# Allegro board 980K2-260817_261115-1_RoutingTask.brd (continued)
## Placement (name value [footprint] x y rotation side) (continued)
NOREF#1103  -  []  258.97 211.91 90 top
NOREF#1104  -  []  238.64 173.37 90 top
NOREF#1105  -  []  206.32 269.17 0 top
NOREF#1106  -  []  173.34 17.15 0 top
NOREF#1107  -  []  276.57 258.18 0 top
NOREF#1108  -  []  266.69 297.01 90 top
NOREF#1109  -  []  268.78 244.35 0 top
NOREF#1110  -  []  186.01 195.7 90 top
NOREF#1111  -  []  231.98 286.59 90 top
NOREF#1112  -  []  201.75 266.13 0 top
NOREF#1113  -  []  236.84 167.33 0 top
NOREF#1114  -  []  196.02 181.47 0 top
NOREF#1115  -  []  244.61 294.89 90 top
NOREF#1116  -  []  283.84 205.58 0 top
NOREF#1117  -  []  235.17 216.75 90 top
NOREF#1118  -  []  150.41 228.7 90 top
NOREF#1119  -  []  259.08 268.59 0 top
NOREF#1120  -  []  279.24 184.35 0 top
NOREF#1121  -  []  239.27 200.97 90 top
NOREF#1122  -  []  136.83 227.03 0 top
NOREF#1123  -  []  224.16 256.43 90 top
NOREF#1124  -  []  180.83 203.76 90 top
NOREF#1125  -  []  146.28 197.85 90 top
NOREF#1126  -  []  280.23 176.17 90 top
NOREF#1127  -  []  263.36 198.18 0 top
NOREF#1128  -  []  197.18 236.17 90 top
NOREF#1129  -  []  149.24 245.31 90 top
NOREF#1130  -  []  273.56 173.37 90 top
NOREF#1131  -  []  153.95 196.75 0 top
NOREF#1132  -  []  187.43 284.11 0 top
NOREF#1133  -  []  147.43 224.11 0 top
NOREF#1134  -  []  241.75 206.13 0 top
NOREF#1135  -  []  268.81 255.7 90 top
NOREF#1136  -  []  187.45 269.24 0 top
NOREF#1137  -  []  253.62 229.09 90 top
NOREF#1138  -  []  228.78 184.35 0 top
NOREF#1139  -  []  273.76 195.7 90 top
NOREF#1140  -  []  279.4 214.54 0 top
NOREF#1141  -  []  173.64 239.09 0 top
NOREF#1142  -  []  134.07 210.89 90 top
NOREF#1143  -  []  283.97 273.09 90 top
NOREF#1144  -  []  222.81 257.6 0 top
NOREF#1145  -  []  229.72 215.77 0 top
NOREF#1146  -  []  239.27 214.21 0 top
NOREF#1147  -  []  188.44 181.72 90 top
NOREF#1148  -  []  272.87 248.11 90 top
NOREF#1149  -  []  174.43 232.23 0 top
NOREF#1150  -  []  192.25 222.59 90 top
NOREF#1151  -  []  150.56 252.5 0 top
NOREF#1152  -  []  193.39 257.85 90 top
NOREF#1153  -  []  258.35 207.01 0 top
NOREF#1154  -  []  232.72 257.6 0 top
NOREF#1155  -  []  135.66 184.35 0 top
NOREF#1156  -  []  155.15 176.17 90 top
NOREF#1157  -  []  239.65 212.56 0 top
NOREF#1158  -  []  199.4 204.45 90 top
NOREF#1159  -  []  267.99 178.35 0 top
NOREF#1160  -  []  203.97 202.09 0 top
NOREF#1161  -  []  259.55 294.49 0 top
NOREF#1162  -  []  227.43 224.11 0 top
NOREF#1163  -  []  155.68 173.69 90 top
NOREF#1164  -  []  243.84 268.62 0 top
NOREF#1165  -  []  128.45 235.2 0 top
NOREF#1166  -  []  208.54 267.5 90 top
NOREF#1167  -  []  164.95 270.32 90 top
NOREF#1168  -  []  234.33 264.33 90 top
NOREF#1169  -  []  169.52 210.32 90 top
NOREF#1170  -  []  192.72 252.78 0 top
NOREF#1171  -  []  216 456.29 90 top
NOREF#1172  -  []  219.08 208.59 0 top
NOREF#1173  -  []  220.43 224.38 90 top
NOREF#1174  -  []  283.84 204.78 90 top
NOREF#1175  -  []  187.77 197.6 0 top
NOREF#1176  -  []  106.58 18.69 90 top
NOREF#1177  -  []  197.03 238.07 0 top
NOREF#1178  -  []  203.97 273.09 90 top
NOREF#1179  -  []  212.87 287.4 90 top
NOREF#1180  -  []  175.24 201.55 90 top
NOREF#1181  -  []  276.52 276.55 0 top
NOREF#1182  -  []  186.96 191.6 90 top
NOREF#1183  -  []  277.37 180.3 90 top
NOREF#1184  -  []  253.62 289.09 90 top
NOREF#1185  -  []  180.95 201.55 90 top
NOREF#1186  -  []  277.25 256.75 0 top
NOREF#1187  -  []  259.39 16.49 0 top
NOREF#1188  -  []  236.02 252.78 0 top
NOREF#1189  -  []  268.35 223.79 90 top
NOREF#1190  -  []  195.68 173.69 0 top
NOREF#1191  -  []  231.11 193.35 0 top
NOREF#1192  -  []  88.16 165.19 0 top
NOREF#1193  -  []  245.38 286.23 0 top
NOREF#1194  -  []  282.26 176.17 90 top
NOREF#1195  -  []  139.08 208.59 0 top
NOREF#1196  -  []  215.84 262.57 90 top
NOREF#1197  -  []  163.84 270.87 90 top
NOREF#1198  -  []  196.57 198.18 0 top
NOREF#1199  -  []  253.36 201.22 0 top
NOREF#1200  -  []  244.61 234.89 90 top
NOREF#1201  -  []  238.11 232.1 0 top
NOREF#1202  -  []  159.4 200.64 90 top
NOREF#1203  -  []  229.84 273.7 0 top
NOREF#1204  -  []  266.96 251.6 90 top
NOREF#1205  -  []  148.32 245.63 90 top
NOREF#1206  -  []  165.38 226.23 0 top
NOREF#1207  -  []  276.02 252.78 0 top
NOREF#1208  -  []  227.8 204.99 90 top
NOREF#1209  -  []  88.16 144.87 0 top
NOREF#1210  -  []  229.67 250.01 0 top
NOREF#1211  -  []  251.05 229.49 0 top
NOREF#1212  -  []  199.72 214.65 90 top
NOREF#1213  -  []  147.77 236.37 0 top
NOREF#1214  -  []  263.49 247.06 90 top
NOREF#1215  -  []  266.16 260.17 90 top
NOREF#1216  -  []  148.78 184.35 0 top
NOREF#1217  -  []  156.54 167 0 top
NOREF#1218  -  []  191.91 256.43 90 top
NOREF#1219  -  []  317.15 392.33 90 top
NOREF#1220  -  []  323.77 454.29 90 top
NOREF#1221  -  []  231.71 171.3 0 top
NOREF#1222  -  []  187.77 241.47 0 top
NOREF#1223  -  []  193.39 253.03 90 top
NOREF#1224  -  []  216 456.29 0 top
NOREF#1225  -  []  168.54 208.95 0 top
NOREF#1226  -  []  179.55 180.49 90 top
NOREF#1227  -  []  263.49 197.85 90 top
NOREF#1228  -  []  269.72 215.77 0 top
NOREF#1229  -  []  149.84 273.7 90 top
NOREF#1230  -  []  248.42 261.77 0 top
NOREF#1231  -  []  230.88 228.6 90 top
NOREF#1232  -  []  261.55 269.94 90 top
NOREF#1233  -  []  209.52 270.32 90 top
NOREF#1234  -  []  252.87 227.4 90 top
NOREF#1235  -  []  168.54 202.09 0 top
NOREF#1236  -  []  227.77 197.6 0 top
NOREF#1237  -  []  236.57 245.63 0 top
NOREF#1238  -  []  268.78 244.35 0 top
NOREF#1239  -  []  269.86 17.15 0 top
NOREF#1240  -  []  183.49 253.03 90 top
NOREF#1241  -  []  186.16 258.18 0 top
NOREF#1242  -  []  148.32 258.18 0 top
NOREF#1243  -  []  254.43 232.23 0 top
NOREF#1244  -  []  130.52 295.42 90 top
NOREF#1245  -  []  259.55 234.49 0 top
NOREF#1246  -  []  168.54 204.45 90 top
NOREF#1247  -  []  186.83 251.93 0 top
NOREF#1248  -  []  324.88 21.69 90 top
NOREF#1249  -  []  231.73 172.54 0 top
NOREF#1250  -  []  236.57 185.63 0 top
NOREF#1251  -  []  160.23 176.17 90 top
NOREF#1252  -  []  237.25 191.93 0 top
NOREF#1253  -  []  194.39 286.59 90 top
NOREF#1254  -  []  239.06 178.07 0 top
NOREF#1255  -  []  157.37 191.6 90 top
NOREF#1256  -  []  171.22 234.89 90 top
NOREF#1257  -  []  254.09 204.23 90 top
NOREF#1258  -  []  203.97 265.9 0 top
NOREF#1259  -  []  195.17 276.75 90 top
NOREF#1260  -  []  156.57 185.63 90 top
NOREF#1261  -  []  269.24 185.31 90 top
NOREF#1262  -  []  243.97 264.45 90 top
NOREF#1263  -  []  208.94 281.73 0 top
NOREF#1264  -  []  203.84 211.67 0 top
NOREF#1265  -  []  288.42 260.97 90 top
NOREF#1266  -  []  271.91 191.6 90 top
NOREF#1267  -  []  89.76 164.74 90 top
NOREF#1268  -  []  231.11 200.17 90 top
NOREF#1269  -  []  156.02 197.6 0 top
NOREF#1270  -  []  150.41 168.7 90 top
NOREF#1271  -  []  216.98 265.11 90 top
NOREF#1272  -  []  157.92 190.01 0 top
NOREF#1273  -  []  163.84 200.97 90 top
NOREF#1274  -  []  270.48 235.77 0 top
NOREF#1275  -  []  277.37 196.43 90 top
NOREF#1276  -  []  283.97 213.09 90 top
NOREF#1277  -  []  161.75 266.13 0 top
NOREF#1278  -  []  139.08 203.76 0 top
NOREF#1279  -  []  123.92 229.94 0 top
NOREF#1280  -  []  189.84 224.11 0 top
NOREF#1281  -  []  279.27 274.21 0 top
NOREF#1282  -  []  122.2 178.35 0 top
NOREF#1283  -  []  129.17 231.95 0 top
NOREF#1284  -  []  250.92 231.95 90 top
NOREF#1285  -  []  151.11 198.18 0 top
NOREF#1286  -  []  106.68 128.02 90 top
NOREF#1287  -  []  188.32 245.63 90 top
NOREF#1288  -  []  155.49 228.7 90 top
NOREF#1289  -  []  227.23 18.69 90 top
NOREF#1290  -  []  269.12 256.43 90 top
NOREF#1291  -  []  179.73 178.35 0 top
NOREF#1292  -  []  172.55 224.49 0 top
NOREF#1293  -  []  157.71 173.69 0 top
NOREF#1294  -  []  232.25 278.02 90 top
NOREF#1295  -  []  222.87 273.02 0 top
NOREF#1296  -  []  265.61 197.6 0 top
NOREF#1297  -  []  156.52 221.12 0 top
NOREF#1298  -  []  283.97 274.54 0 top
NOREF#1299  -  []  132.26 248.4 0 top
NOREF#1300  -  []  224.16 191.6 90 top
NOREF#1301  -  []  153.95 191.93 0 top
NOREF#1302  -  []  192.13 224.66 0 top
NOREF#1303  -  []  188.78 184.35 0 top
NOREF#1304  -  []  163.97 204.45 90 top
NOREF#1305  -  []  196.02 197.6 0 top
NOREF#1306  -  []  271.98 286.59 90 top
NOREF#1307  -  []  231.79 251.93 0 top
NOREF#1308  -  []  100.95 17.15 0 top
NOREF#1309  -  []  190.56 197.6 0 top
NOREF#1310  -  []  218.95 204.09 0 top
NOREF#1311  -  []  114.61 17.78 0 top
NOREF#1312  -  []  266.96 256.43 90 top
NOREF#1313  -  []  135.43 276.18 0 top
NOREF#1314  -  []  196.8 274.65 90 top
NOREF#1315  -  []  124.32 291.95 90 top
NOREF#1316  -  []  283.97 267.5 90 top
NOREF#1317  -  []  152.63 172.86 0 top
NOREF#1318  -  []  124.44 232.28 90 top
NOREF#1319  -  []  201.75 272.22 0 top
NOREF#1320  -  []  279.4 274.54 0 top
NOREF#1321  -  []  226.96 196.43 90 top
NOREF#1322  -  []  148.99 256.75 0 top
NOREF#1323  -  []  211.25 244.35 0 top
NOREF#1324  -  []  149.84 213.7 90 top
NOREF#1325  -  []  271.11 260.17 90 top
NOREF#1326  -  []  276.8 274.65 90 top
NOREF#1327  -  []  202.85 237.22 0 top
NOREF#1328  -  []  281.41 227.9 90 top
NOREF#1329  -  []  251.05 232.28 90 top
NOREF#1330  -  []  229.72 281.62 0 top
NOREF#1331  -  []  235.92 190.88 90 top
NOREF#1332  -  []  221.55 262.57 90 top
NOREF#1333  -  []  186.28 253.03 90 top
NOREF#1334  -  []  279.4 273.09 90 top
NOREF#1335  -  []  157.5 185.31 90 top
NOREF#1336  -  []  258.83 292.23 0 top
NOREF#1337  -  []  171.05 185.49 90 top
NOREF#1338  -  []  226.01 195.7 90 top
NOREF#1339  -  []  188.44 253.03 90 top
NOREF#1340  -  []  156.84 227.33 0 top
NOREF#1341  -  []  208.54 200.64 90 top
NOREF#1342  -  []  180.59 184.98 90 top
NOREF#1343  -  []  167.74 396.29 0 top
NOREF#1344  -  []  278.91 172.21 90 top
NOREF#1345  -  []  236.57 253.35 0 top
NOREF#1346  -  []  241.75 209.17 0 top
NOREF#1347  -  []  258.95 201.55 0 top
NOREF#1348  -  []  138.35 204.47 0 top
NOREF#1349  -  []  175.24 261.55 90 top
NOREF#1350  -  []  155.05 283.39 0 top
NOREF#1351  -  []  156.7 197.85 90 top
NOREF#1352  -  []  248.54 264.45 90 top
NOREF#1353  -  []  196.5 392.33 90 top
NOREF#1354  -  []  180.83 265.79 90 top
NOREF#1355  -  []  163.97 270.55 90 top
NOREF#1356  -  []  270.77 219.22 90 top
NOREF#1357  -  []  271.76 167.33 0 top
NOREF#1358  -  []  248.54 265.9 0 top
NOREF#1359  -  []  164.44 292.28 90 top
NOREF#1360  -  []  276.57 253.35 0 top
NOREF#1361  -  []  161.75 269.17 0 top
NOREF#1362  -  []  279.27 201.77 0 top
NOREF#1363  -  []  250.89 262.32 0 top
NOREF#1364  -  []  191.11 253.35 0 top
NOREF#1365  -  []  191.19 218.07 0 top
NOREF#1366  -  []  268.78 288.49 0 top
NOREF#1367  -  []  227.3 226.19 0 top
NOREF#1368  -  []  189.84 213.7 90 top
NOREF#1369  -  []  184.04 251.93 0 top
NOREF#1370  -  []  145.61 197.6 0 top
NOREF#1371  -  []  168.94 221.73 0 top
NOREF#1372  -  []  109.55 389.27 90 top
NOREF#1373  -  []  251.05 292.28 90 top
NOREF#1374  -  []  264.04 256.75 0 top
NOREF#1375  -  []  225.61 257.6 0 top
NOREF#1376  -  []  167.04 299.09 0 top
NOREF#1377  -  []  185.41 213.02 90 top
NOREF#1378  -  []  226.16 258.18 0 top
NOREF#1379  -  []  196.8 225.06 90 top
NOREF#1380  -  []  149.72 286.19 0 top
NOREF#1381  -  []  150.6 173.69 0 top
NOREF#1382  -  []  207.04 299.09 0 top
NOREF#1383  -  []  275.15 236.17 90 top
NOREF#1384  -  []  152.25 218.02 0 top
NOREF#1385  -  []  151.91 256.43 90 top
NOREF#1386  -  []  279.22 190.88 90 top
NOREF#1387  -  []  243.97 207.5 90 top
NOREF#1388  -  []  231.46 167 0 top
NOREF#1389  -  []  220.43 284.38 90 top
NOREF#1390  -  []  152.25 222.59 0 top
NOREF#1391  -  []  153.56 233.37 90 top
NOREF#1392  -  []  212.55 190.49 90 top
NOREF#1393  -  []  273.94 251.93 0 top
NOREF#1394  -  []  231.24 193.03 90 top
NOREF#1395  -  []  255.11 261.22 90 top
NOREF#1396  -  []  236.8 285.06 90 top
NOREF#1397  -  []  241.41 167.9 90 top
NOREF#1398  -  []  248.54 260.64 90 top
NOREF#1399  -  []  229.12 240.3 90 top
NOREF#1400  -  []  266.83 196.75 0 top
NOREF#1401  -  []  196.33 167.9 90 top
NOREF#1402  -  []  128.48 456.29 0 top
NOREF#1403  -  []  156.1 280.99 90 top
NOREF#1404  -  []  231.53 173.37 90 top
NOREF#1405  -  []  191.98 226.59 90 top
NOREF#1406  -  []  274.07 196.43 90 top
NOREF#1407  -  []  271.19 218.07 0 top
NOREF#1408  -  []  216.55 254.49 90 top
NOREF#1409  -  []  199.4 268.95 0 top
NOREF#1410  -  []  209.52 210.32 90 top
NOREF#1411  -  []  139.72 213.6 90 top
NOREF#1412  -  []  185.61 252.78 0 top
NOREF#1413  -  []  272.11 231.4 0 top
NOREF#1414  -  []  142.03 289.03 90 top
NOREF#1415  -  []  239.27 268.62 0 top
NOREF#1416  -  []  134.51 203.76 0 top
NOREF#1417  -  []  148.99 240.62 0 top
NOREF#1418  -  []  209.05 292.28 0 top
NOREF#1419  -  []  242.44 232.28 0 top
NOREF#1420  -  []  187.8 265.39 90 top
NOREF#1421  -  []  239.4 214.54 0 top
NOREF#1422  -  []  231.53 233.37 90 top
NOREF#1423  -  []  186.7 283.04 90 top
NOREF#1424  -  []  156.61 233.37 90 top
NOREF#1425  -  []  187.77 257.6 0 top
NOREF#1426  -  []  248.54 268.95 0 top
NOREF#1427  -  []  146.17 226.14 90 top
NOREF#1428  -  []  223.36 253.35 0 top
NOREF#1429  -  []  195.68 233.69 0 top
NOREF#1430  -  []  191.11 258.18 0 top
NOREF#1431  -  []  237.04 244.35 0 top
NOREF#1432  -  []  181.85 232.5 0 top
NOREF#1433  -  []  235.17 281.32 90 top
NOREF#1434  -  []  159.4 260.64 90 top
NOREF#1435  -  []  164.95 272.86 90 top
NOREF#1436  -  []  208.42 204.78 90 top
NOREF#1437  -  []  178.97 271.91 90 top
NOREF#1438  -  []  221.59 234.15 0 top
NOREF#1439  -  []  242.57 231.95 0 top
NOREF#1440  -  []  206.32 212.22 0 top
NOREF#1441  -  []  205.38 226.23 0 top
NOREF#1442  -  []  179.08 201.22 0 top
NOREF#1443  -  []  269.72 275.77 0 top
NOREF#1444  -  []  195.17 216.75 90 top
NOREF#1445  -  []  172.37 392.33 90 top
NOREF#1446  -  []  159.4 273.09 90 top
NOREF#1447  -  []  243.97 267.5 90 top
NOREF#1448  -  []  176.38 204.09 90 top
NOREF#1449  -  []  274.33 267.37 90 top
NOREF#1450  -  []  214.43 232.23 0 top
NOREF#1451  -  []  236.52 221.12 0 top
NOREF#1452  -  []  277.37 256.43 90 top
NOREF#1453  -  []  277.59 175.77 0 top
NOREF#1454  -  []  318.12 17.15 0 top
NOREF#1455  -  []  187.43 284.11 90 top
NOREF#1456  -  []  148.44 253.03 90 top
NOREF#1457  -  []  254.09 267.27 90 top
NOREF#1458  -  []  260.95 206.12 90 top
NOREF#1459  -  []  222.81 252.78 0 top
NOREF#1460  -  []  235.68 233.69 0 top
NOREF#1461  -  []  269.55 248.99 90 top
NOREF#1462  -  []  133.24 261.55 0 top
NOREF#1463  -  []  261.55 262.57 90 top
NOREF#1464  -  []  227.43 224.11 90 top
NOREF#1465  -  []  199.4 213.09 90 top
NOREF#1466  -  []  231.76 227.33 0 top
NOREF#1467  -  []  149.84 279.54 0 top
NOREF#1468  -  []  135.82 266.44 0 top
NOREF#1469  -  []  271.11 198.18 0 top
NOREF#1470  -  []  253.64 299.09 0 top
NOREF#1471  -  []  239.27 267.82 90 top
NOREF#1472  -  []  163.84 201.77 0 top
NOREF#1473  -  []  276.8 225.06 90 top
NOREF#1474  -  []  226.01 250.88 90 top
NOREF#1475  -  []  151.46 227 0 top
NOREF#1476  -  []  272.13 280.09 0 top
NOREF#1477  -  []  236.02 181.47 0 top
NOREF#1478  -  []  279.4 202.09 0 top
NOREF#1479  -  []  254.09 200.42 90 top
NOREF#1480  -  []  173.36 201.22 0 top
NOREF#1481  -  []  278.11 232.1 0 top
NOREF#1482  -  []  154.39 226.59 90 top
NOREF#1483  -  []  220.95 261.55 90 top
NOREF#1484  -  []  193.76 250.88 90 top
NOREF#1485  -  []  268.19 187.71 0 top
NOREF#1486  -  []  138.85 181.15 90 top
NOREF#1487  -  []  168.54 200.64 90 top
NOREF#1488  -  []  288.42 261.77 0 top
NOREF#1489  -  []  180.95 264.09 90 top
NOREF#1490  -  []  155.58 202.67 90 top
NOREF#1491  -  []  237.71 233.69 90 top
NOREF#1492  -  []  275.17 272.17 90 top
NOREF#1493  -  []  177.29 247.78 0 top
NOREF#1494  -  []  169.17 231.95 0 top
NOREF#1495  -  []  273.39 193.03 90 top
NOREF#1496  -  []  261.55 202.57 90 top
NOREF#1497  -  []  85.84 157.62 0 top
NOREF#1498  -  []  243.84 265.58 0 top
NOREF#1499  -  []  268.44 253.03 90 top
NOREF#1500  -  []  193.76 255.7 90 top
NOREF#1501  -  []  147.43 284.11 0 top
NOREF#1502  -  []  178.97 18.69 0 top
NOREF#1503  -  []  232.13 224.66 0 top
NOREF#1504  -  []  261.85 246.47 0 top
NOREF#1505  -  []  154.33 267.37 90 top
NOREF#1506  -  []  151.24 253.03 90 top
NOREF#1507  -  []  151.95 178.07 0 top
NOREF#1508  -  []  184.16 191.6 90 top
NOREF#1509  -  []  156.7 241.72 90 top
NOREF#1510  -  []  230.2 389.27 90 top
NOREF#1511  -  []  276.7 197.85 90 top
NOREF#1512  -  []  236.57 185.63 90 top
NOREF#1513  -  []  222.6 82.65 0 top
NOREF#1514  -  []  217.25 236.5 90 top
NOREF#1515  -  []  122.44 292.28 0 top
NOREF#1516  -  []  220.63 392.33 90 top
NOREF#1517  -  []  267.77 241.47 0 top
NOREF#1518  -  []  106.83 148.19 90 top
NOREF#1519  -  []  137.28 272.5 0 top
NOREF#1520  -  []  266.01 184.91 90 top
NOREF#1521  -  []  169.52 270.32 90 top
NOREF#1522  -  []  241.75 212.22 0 top
NOREF#1523  -  []  254.43 292.23 0 top
NOREF#1524  -  []  163.4 296.38 0 top
NOREF#1525  -  []  278.64 173.37 90 top
NOREF#1526  -  []  150.88 168.6 90 top
NOREF#1527  -  []  197.71 233.69 90 top
NOREF#1528  -  []  159.4 268.95 0 top
NOREF#1529  -  []  293.99 17.15 90 top
NOREF#1530  -  []  191.98 280.75 90 top
NOREF#1531  -  []  272.11 171.4 0 top
NOREF#1532  -  []  184.04 185.96 0 top
NOREF#1533  -  []  236.84 227.33 0 top
NOREF#1534  -  []  226.01 190.88 90 top
NOREF#1535  -  []  191.85 18.69 0 top
NOREF#1536  -  []  185.41 273.02 90 top
NOREF#1537  -  []  224.04 245.96 0 top
NOREF#1538  -  []  150.21 82.65 0 top
NOREF#1539  -  []  226.16 226.14 90 top
NOREF#1540  -  []  168.54 265.9 0 top
NOREF#1541  -  []  139.55 240.49 90 top
NOREF#1542  -  []  186.7 223.05 90 top
NOREF#1543  -  []  276.38 181.15 90 top
NOREF#1544  -  []  156.79 231.3 0 top
NOREF#1545  -  []  155.05 278.82 0 top
NOREF#1546  -  []  268.32 242.05 0 top
NOREF#1547  -  []  235.56 175.77 0 top
NOREF#1548  -  []  149.84 224.11 0 top
NOREF#1549  -  []  194.33 207.37 90 top
NOREF#1550  -  []  179.08 268.59 0 top
NOREF#1551  -  []  236.33 167.9 90 top
NOREF#1552  -  []  250.89 209.17 0 top
NOREF#1553  -  []  197.04 244.35 0 top
NOREF#1554  -  []  235.05 278.82 0 top
NOREF#1555  -  []  279.06 178.07 0 top
NOREF#1556  -  []  138.74 83.81 0 top
NOREF#1557  -  []  177.29 187.78 0 top
NOREF#1558  -  []  237.74 226.35 90 top
NOREF#1559  -  []  125.04 233.3 90 top
NOREF#1560  -  []  243.97 214.54 0 top
NOREF#1561  -  []  89.74 135.6 90 top
NOREF#1562  -  []  136.55 194.49 90 top
NOREF#1563  -  []  226.83 196.75 0 top
NOREF#1564  -  []  239.4 212 0 top
NOREF#1565  -  []  237.37 256.43 90 top
NOREF#1566  -  []  159.4 264.45 90 top
NOREF#1567  -  []  203.84 273.41 90 top
NOREF#1568  -  []  260.43 284.38 90 top
NOREF#1569  -  []  156.8 225.06 90 top
NOREF#1570  -  []  268.78 184.35 0 top
NOREF#1571  -  []  152.87 188.11 90 top
NOREF#1572  -  []  239.4 270.55 90 top
NOREF#1573  -  []  171.05 232.28 90 top
NOREF#1574  -  []  151.98 226.59 90 top
NOREF#1575  -  []  106.68 148.34 90 top
NOREF#1576  -  []  151.91 191.6 90 top
NOREF#1577  -  []  160.23 236.17 90 top
NOREF#1578  -  []  193.03 232.1 0 top
NOREF#1579  -  []  221.6 17.15 0 top
NOREF#1580  -  []  196.02 252.78 0 top
NOREF#1581  -  []  262.81 246.81 0 top
NOREF#1582  -  []  182.03 229.03 90 top
NOREF#1583  -  []  140.95 206.12 90 top
NOREF#1584  -  []  220.83 265.79 90 top
NOREF#1585  -  []  251.25 244.35 0 top
NOREF#1586  -  []  262.03 229.03 90 top
NOREF#1587  -  []  149.67 236.37 90 top
NOREF#1588  -  []  149.84 273.7 0 top
NOREF#1589  -  []  239.4 267.5 90 top
NOREF#1590  -  []  230.97 179.57 90 top
NOREF#1591  -  []  223.89 245.24 90 top
NOREF#1592  -  []  150.97 195.7 90 top
NOREF#1593  -  []  272.87 188.11 90 top
NOREF#1594  -  []  219.08 203.76 0 top
NOREF#1595  -  []  228.99 256.75 0 top
NOREF#1596  -  []  243.97 210.55 90 top
NOREF#1597  -  []  155.05 218.82 0 top
NOREF#1598  -  []  279.4 262.09 0 top
NOREF#1599  -  []  168.54 207.5 90 top
NOREF#1600  -  []  266.01 195.7 90 top
NOREF#1601  -  []  281.44 244.35 0 top
NOREF#1602  -  []  172.64 264.47 0 top
NOREF#1603  -  []  258.35 269.04 0 top
NOREF#1604  -  []  196.7 197.85 90 top
NOREF#1605  -  []  239.4 268.95 0 top
NOREF#1606  -  []  178.83 292.23 0 top
NOREF#1607  -  []  263.36 253.35 0 top
NOREF#1608  -  []  180.83 201.22 90 top
NOREF#1609  -  []  145.61 252.5 0 top
NOREF#1610  -  []  214.51 203.76 0 top
NOREF#1611  -  []  273.6 226.96 0 top
NOREF#1612  -  []  218.35 264.47 0 top
NOREF#1613  -  []  168.54 264.45 90 top
NOREF#1614  -  []  186.16 198.18 0 top
NOREF#1615  -  []  201.44 244.35 0 top
NOREF#1616  -  []  240.13 396.29 0 top
NOREF#1617  -  []  243.84 273.41 90 top
NOREF#1618  -  []  137.29 187.78 0 top
NOREF#1619  -  []  125.08 17.15 90 top
NOREF#1620  -  []  174.43 292.23 0 top
NOREF#1621  -  []  224.04 251.93 0 top
NOREF#1622  -  []  221.55 207.14 90 top
NOREF#1623  -  []  176.98 265.11 90 top
NOREF#1624  -  []  288.54 264.45 90 top
NOREF#1625  -  []  157.18 176.17 90 top
NOREF#1626  -  []  265.09 197.49 90 top
NOREF#1627  -  []  275.17 216.75 90 top
NOREF#1628  -  []  158.64 233.37 90 top
NOREF#1629  -  []  235.27 458.49 0 top
NOREF#1630  -  []  89.74 155.92 0 top
NOREF#1631  -  []  141.55 205.11 90 top
NOREF#1632  -  []  176.98 205.11 90 top
NOREF#1633  -  []  159.24 184.35 0 top
NOREF#1634  -  []  279.27 214.21 0 top
NOREF#1635  -  []  163.84 210.87 90 top
NOREF#1636  -  []  156.57 198.18 0 top
NOREF#1637  -  []  182.87 286.99 0 top
NOREF#1638  -  []  275.05 274.25 0 top
NOREF#1639  -  []  239.27 210.87 90 top
NOREF#1640  -  []  161.75 272.22 0 top
NOREF#1641  -  []  182.87 273.02 0 top
NOREF#1642  -  []  248.42 200.97 90 top
NOREF#1643  -  []  211.25 184.35 0 top
NOREF#1644  -  []  156.7 253.03 90 top
NOREF#1645  -  []  163.97 200.64 90 top
NOREF#1646  -  []  163.97 205.9 0 top
NOREF#1647  -  []  139.55 234.49 0 top
NOREF#1648  -  []  189.12 191.6 90 top
NOREF#1649  -  []  159.27 267.82 90 top
NOREF#1650  -  []  215.59 16.49 0 top
NOREF#1651  -  []  196.57 245.63 0 top
NOREF#1652  -  []  188.35 217.95 90 top
NOREF#1653  -  []  234.78 236.5 90 top
NOREF#1654  -  []  243.84 270.87 90 top
NOREF#1655  -  []  192.66 226.35 90 top
NOREF#1656  -  []  276.8 285.06 90 top
NOREF#1657  -  []  178.95 261.55 0 top
NOREF#1658  -  []  283.97 270.55 90 top
NOREF#1659  -  []  199.4 200.64 90 top
NOREF#1660  -  []  139.08 261.22 0 top
NOREF#1661  -  []  159.27 270.87 90 top
NOREF#1662  -  []  151.18 179.15 0 top
NOREF#1663  -  []  138.95 268.91 0 top
NOREF#1664  -  []  213.75 452.29 90 top
NOREF#1665  -  []  62.86 375.04 0 top
NOREF#1666  -  []  203.84 201.77 0 top
NOREF#1667  -  []  124.61 294.24 90 top
NOREF#1668  -  []  159.4 272 0 top
NOREF#1669  -  []  208.42 264.78 90 top
NOREF#1670  -  []  271.98 280.75 90 top
NOREF#1671  -  []  220.95 208.91 90 top
NOREF#1672  -  []  131.65 233.3 90 top
NOREF#1673  -  []  159.22 195.7 90 top
NOREF#1674  -  []  288.54 205.9 0 top
NOREF#1675  -  []  188.35 223.79 90 top
NOREF#1676  -  []  279.27 200.97 90 top
NOREF#1677  -  []  129.36 361.96 0 top
NOREF#1678  -  []  279.4 264.45 90 top
NOREF#1679  -  []  190.56 257.6 0 top
NOREF#1680  -  []  190.77 283.79 90 top
NOREF#1681  -  []  214.09 200.42 90 top
NOREF#1682  -  []  268.32 182.05 0 top
NOREF#1683  -  []  268.78 222.65 0 top
NOREF#1684  -  []  288.54 204.45 90 top
NOREF#1685  -  []  236.8 225.06 90 top
NOREF#1686  -  []  264.04 191.93 0 top
NOREF#1687  -  []  241.44 244.35 0 top
NOREF#1688  -  []  236.7 197.85 90 top
NOREF#1689  -  []  247.95 226.12 90 top
NOREF#1690  -  []  230.77 283.79 90 top
NOREF#1691  -  []  153.83 172.21 90 top
NOREF#1692  -  []  266.28 253.03 90 top
NOREF#1693  -  []  152.72 252.5 0 top
NOREF#1694  -  []  267.43 218.27 0 top
NOREF#1695  -  []  283.84 201.77 0 top
NOREF#1696  -  []  118.64 291.4 0 top
NOREF#1697  -  []  274.39 282.02 90 top
NOREF#1698  -  []  283.04 176.5 90 top
NOREF#1699  -  []  203.04 236.5 90 top
NOREF#1700  -  []  239.27 260.97 90 top
NOREF#1701  -  []  224.04 256.75 0 top
NOREF#1702  -  []  231.24 257.85 90 top
NOREF#1703  -  []  180.95 204.09 90 top
NOREF#1704  -  []  226.28 193.03 90 top
NOREF#1705  -  []  163.97 210.55 90 top
NOREF#1706  -  []  284.95 260.42 90 top
NOREF#1707  -  []  146.01 190.88 90 top
NOREF#1708  -  []  234.39 286.59 90 top
NOREF#1709  -  []  270.6 233.69 90 top
NOREF#1710  -  []  196.54 167 0 top
NOREF#1711  -  []  235.05 223.39 0 top
NOREF#1712  -  []  266.01 244.91 90 top
NOREF#1713  -  []  190.97 190.88 90 top
NOREF#1714  -  []  279.44 239.15 0 top
NOREF#1715  -  []  136.26 203.76 90 top
NOREF#1716  -  []  239.22 190.88 90 top
NOREF#1717  -  []  283.52 83.81 0 top
NOREF#1718  -  []  166.32 274.76 0 top
NOREF#1719  -  []  278.13 389.27 90 top
NOREF#1720  -  []  218.35 207.01 0 top
NOREF#1721  -  []  170.89 209.17 0 top
NOREF#1722  -  []  263.89 245.24 90 top
NOREF#1723  -  []  182.87 213.02 0 top
NOREF#1724  -  []  146.16 198.18 0 top
NOREF#1725  -  []  219.08 268.59 0 top
NOREF#1726  -  []  219.72 213.6 90 top
NOREF#1727  -  []  268.32 185.63 0 top
NOREF#1728  -  []  266.01 255.7 90 top
NOREF#1729  -  []  256.55 254.49 90 top
NOREF#1730  -  []  272.25 222.59 0 top
NOREF#1731  -  []  243.84 261.77 0 top
NOREF#1732  -  []  267.9 265.84 90 top
NOREF#1733  -  []  159.27 261.77 0 top
NOREF#1734  -  []  236.7 181.72 90 top
NOREF#1735  -  []  264.04 196.75 0 top
NOREF#1736  -  []  283.84 273.41 90 top
NOREF#1737  -  []  161.75 262.32 0 top
NOREF#1738  -  []  187.43 218.27 0 top
NOREF#1739  -  []  190.77 279.22 90 top
NOREF#1740  -  []  271.19 278.07 0 top
NOREF#1741  -  []  159.27 260.97 90 top
NOREF#1742  -  []  168.42 204.78 90 top
NOREF#1743  -  []  140.83 265.79 90 top
NOREF#1744  -  []  203.84 213.41 90 top
NOREF#1745  -  []  123.91 295.42 90 top
NOREF#1746  -  []  240.13 456.29 0 top
NOREF#1747  -  []  178.95 264.09 0 top
NOREF#1748  -  []  227.99 178.35 0 top
NOREF#1749  -  []  133.66 179.15 0 top
NOREF#1750  -  []  281.75 269.17 0 top
NOREF#1751  -  []  176.63 292.23 0 top
NOREF#1752  -  []  211.21 234.89 90 top
NOREF#1753  -  []  272.25 218.02 0 top
NOREF#1754  -  []  149.68 334.65 0 top
NOREF#1755  -  []  235.17 276.75 0 top
NOREF#1756  -  []  237.37 196.43 90 top
NOREF#1757  -  []  279.27 205.58 0 top
NOREF#1758  -  []  163.97 207.5 90 top
NOREF#1759  -  []  149.12 191.6 90 top
NOREF#1760  -  []  157.04 244.35 0 top
NOREF#1761  -  []  165.38 286.23 0 top
NOREF#1762  -  []  221.59 248.12 0 top
NOREF#1763  -  []  146.83 196.75 0 top
NOREF#1764  -  []  233.27 253.35 0 top
NOREF#1765  -  []  128.94 221.73 0 top
NOREF#1766  -  []  203.4 236.38 0 top
NOREF#1767  -  []  265.61 257.6 0 top
NOREF#1768  -  []  231.95 238.07 0 top
NOREF#1769  -  []  211.65 293.3 90 top
NOREF#1770  -  []  208.42 201.77 0 top
NOREF#1771  -  []  147.3 226.19 0 top
NOREF#1772  -  []  270.97 195.7 90 top
NOREF#1773  -  []  152.25 272.17 90 top
NOREF#1774  -  []  191.76 167.33 0 top
NOREF#1775  -  []  259.08 201.22 0 top
NOREF#1776  -  []  209.05 232.28 0 top
NOREF#1777  -  []  208.42 268.62 0 top
NOREF#1778  -  []  188.78 184.35 0 top
NOREF#1779  -  []  222.81 197.6 0 top
NOREF#1780  -  []  276.8 220.49 90 top
NOREF#1781  -  []  152.13 274.25 0 top
NOREF#1782  -  []  218.95 268.91 0 top
NOREF#1783  -  []  253.45 184.35 0 top
NOREF#1784  -  []  288.54 207.5 90 top
NOREF#1785  -  []  148.19 247.71 0 top
NOREF#1786  -  []  234.33 207.37 90 top
NOREF#1787  -  []  235.96 168.6 90 top
NOREF#1788  -  []  238.11 172.1 0 top
NOREF#1789  -  []  130.92 231.95 90 top
NOREF#1790  -  []  168.54 268.95 0 top
NOREF#1791  -  []  174.38 264.09 0 top
NOREF#1792  -  []  135.15 265.24 90 top
NOREF#1793  -  []  248.94 281.73 0 top
NOREF#1794  -  []  162.87 16.49 0 top
NOREF#1795  -  []  236.7 193.03 90 top
NOREF#1796  -  []  252.55 284.49 0 top
NOREF#1797  -  []  247.95 286.12 90 top
NOREF#1798  -  []  194.78 176.5 90 top
NOREF#1799  -  []  187.45 209.24 0 top
NOREF#1800  -  []  271.98 220.75 90 top
NOREF#1801  -  []  158.11 172.1 0 top
NOREF#1802  -  []  279.4 207.5 90 top
NOREF#1803  -  []  236.79 231.3 0 top
NOREF#1804  -  []  246.32 272.22 0 top
NOREF#1805  -  []  187.8 269.99 0 top
NOREF#1806  -  []  233.94 196.75 0 top
NOREF#1807  -  []  191.24 193.03 90 top
NOREF#1808  -  []  155.97 21.69 90 top
NOREF#1809  -  []  181.55 269.94 90 top
NOREF#1810  -  []  277.04 184.35 0 top
NOREF#1811  -  []  196.7 253.03 90 top
NOREF#1812  -  []  239.72 223.79 90 top
NOREF#1813  -  []  277.71 173.69 90 top
NOREF#1814  -  []  168.42 264.78 90 top
NOREF#1815  -  []  243.97 204.45 90 top
NOREF#1816  -  []  85.84 137.3 0 top
NOREF#1817  -  []  224.16 196.43 90 top
NOREF#1818  -  []  273.18 211.85 90 top
NOREF#1819  -  []  150.15 266.89 90 top
NOREF#1820  -  []  214.09 260.42 90 top
NOREF#1821  -  []  239.4 213.09 90 top
NOREF#1822  -  []  163.97 272 0 top
NOREF#1823  -  []  273.18 244.35 0 top
NOREF#1824  -  []  150.6 173.69 90 top
NOREF#1825  -  []  279.27 213.41 90 top
NOREF#1826  -  []  273.39 197.85 90 top
NOREF#1827  -  []  247.98 226.38 90 top
NOREF#1828  -  []  235.17 212.18 90 top
NOREF#1829  -  []  159.4 274.54 0 top
NOREF#1830  -  []  189.67 250.01 0 top
NOREF#1831  -  []  182.87 226.99 0 top
NOREF#1832  -  []  167.74 456.29 90 top
NOREF#1833  -  []  260.83 268.59 90 top
NOREF#1834  -  []  174.04 270.63 90 top
NOREF#1835  -  []  139.08 205.79 0 top
NOREF#1836  -  []  255.24 201.55 90 top
NOREF#1837  -  []  173.36 261.22 0 top
NOREF#1838  -  []  243.84 210.87 90 top
NOREF#1839  -  []  259.08 263.76 0 top
NOREF#1840  -  []  262.87 286.99 0 top
NOREF#1841  -  []  147.45 269.24 0 top
NOREF#1842  -  []  148.35 283.79 90 top
NOREF#1843  -  []  190.48 235.77 0 top
NOREF#1844  -  []  157.81 389.27 90 top
NOREF#1845  -  []  243.97 262.09 0 top
NOREF#1846  -  []  124.11 392.33 90 top
NOREF#1847  -  []  269.67 190.01 0 top
NOREF#1848  -  []  230.15 266.89 90 top
NOREF#1849  -  []  229.84 213.7 0 top
NOREF#1850  -  []  219.08 261.22 0 top
NOREF#1851  -  []  133.1 237.5 0 top
NOREF#1852  -  []  266.16 226.14 90 top
NOREF#1853  -  []  149.12 251.6 90 top
NOREF#1854  -  []  199.72 283.79 90 top
NOREF#1855  -  []  168.42 207.82 90 top
NOREF#1856  -  []  203.84 207.82 90 top
NOREF#1857  -  []  273.83 172.21 90 top
NOREF#1858  -  []  193.76 190.88 90 top
NOREF#1859  -  []  267.99 238.35 0 top
NOREF#1860  -  []  272.72 197.6 0 top
NOREF#1861  -  []  130.58 263.21 90 top
NOREF#1862  -  []  273.27 198.18 0 top
NOREF#1863  -  []  187.05 269.24 0 top
NOREF#1864  -  []  276.02 197.6 0 top
NOREF#1865  -  []  230.98 184.35 0 top
NOREF#1866  -  []  119.48 456.29 0 top
NOREF#1867  -  []  195.05 214.25 0 top
NOREF#1868  -  []  269.84 213.7 0 top
NOREF#1869  -  []  231.76 167.33 0 top
NOREF#1870  -  []  197.47 17.15 0 top
NOREF#1871  -  []  209.17 231.95 0 top
NOREF#1872  -  []  149.67 247.68 90 top
NOREF#1873  -  []  163.97 262.09 0 top
NOREF#1874  -  []  288.39 452.29 90 top
NOREF#1875  -  []  171.65 293.3 90 top
NOREF#1876  -  []  181.6 294.14 0 top
NOREF#1877  -  []  260.83 263.76 90 top
NOREF#1878  -  []  289.52 272.86 90 top
NOREF#1879  -  []  226.28 253.03 90 top
NOREF#1880  -  []  187.01 458.49 0 top
NOREF#1881  -  []  227.77 192.78 0 top
NOREF#1882  -  []  227.43 284.11 90 top
NOREF#1883  -  []  218.95 264.09 0 top
NOREF#1884  -  []  150.56 192.78 0 top
NOREF#1885  -  []  266.16 272.17 90 top
NOREF#1886  -  []  166.32 266.13 0 top
NOREF#1887  -  []  203.97 207.5 90 top
NOREF#1888  -  []  181.03 207.69 90 top
NOREF#1889  -  []  266.28 257.85 90 top
NOREF#1890  -  []  209.52 200.42 90 top
NOREF#1891  -  []  171.25 244.35 0 top
NOREF#1892  -  []  270.97 179.57 90 top
NOREF#1893  -  []  178.97 18.69 90 top
NOREF#1894  -  []  213.62 289.09 90 top
NOREF#1895  -  []  225.41 213.02 90 top
NOREF#1896  -  []  226.96 256.43 90 top
NOREF#1897  -  []  209.52 272.86 90 top
NOREF#1898  -  []  196.1 276.42 90 top
NOREF#1899  -  []  199.65 272.56 0 top
NOREF#1900  -  []  277.25 180.62 0 top
NOREF#1901  -  []  236.54 227 0 top
NOREF#1902  -  []  260.83 265.79 90 top
NOREF#1903  -  []  153.18 222.26 90 top
NOREF#1904  -  []  228.44 241.72 90 top
NOREF#1905  -  []  204.95 267.27 90 top
NOREF#1906  -  []  156.38 181.15 90 top
NOREF#1907  -  []  267.8 269.99 0 top
NOREF#1908  -  []  183.36 187.38 0 top
NOREF#1909  -  []  186.16 212.17 90 top
NOREF#1910  -  []  199.27 204.78 90 top
NOREF#1911  -  []  155.17 221.32 0 top
NOREF#1912  -  []  199.44 179.15 0 top
NOREF#1913  -  []  249.05 232.28 0 top
NOREF#1914  -  []  258.35 271.84 0 top
NOREF#1915  -  []  191.24 257.85 90 top
NOREF#1916  -  []  197.25 191.93 0 top
NOREF#1917  -  []  275.68 233.69 0 top
NOREF#1918  -  []  270.97 255.7 90 top
NOREF#1919  -  []  156.57 245.63 90 top
NOREF#1920  -  []  270.56 192.78 0 top
NOREF#1921  -  []  178.35 271.84 0 top
NOREF#1922  -  []  275.92 250.88 90 top
NOREF#1923  -  []  183.36 198.18 0 top
NOREF#1924  -  []  279.27 268.62 0 top
NOREF#1925  -  []  163.84 265.58 0 top
NOREF#1926  -  []  123.4 281.8 0 top
NOREF#1927  -  []  101.95 82.65 0 top
NOREF#1928  -  []  193.98 178.07 0 top
NOREF#1929  -  []  189.24 185.31 90 top
NOREF#1930  -  []  233.18 184.35 0 top
NOREF#1931  -  []  153.76 195.7 90 top
NOREF#1932  -  []  80.49 155.57 0 top
NOREF#1933  -  []  163.84 260.97 90 top
NOREF#1934  -  []  163.84 271.67 0 top
NOREF#1935  -  []  237.71 173.69 90 top
NOREF#1936  -  []  190.15 206.89 90 top
NOREF#1937  -  []  191.98 220.75 90 top
NOREF#1938  -  []  173.64 299.09 0 top
NOREF#1939  -  []  253.65 179.15 0 top
NOREF#1940  -  []  266.16 198.18 0 top
NOREF#1941  -  []  286.32 266.13 0 top
NOREF#1942  -  []  231.98 226.59 90 top
NOREF#1943  -  []  321.52 456.29 0 top
NOREF#1944  -  []  232.25 218.02 90 top
NOREF#1945  -  []  267.05 269.24 0 top
NOREF#1946  -  []  244.64 241.15 90 top
NOREF#1947  -  []  191.11 200.17 90 top
NOREF#1948  -  []  233.27 193.35 0 top
NOREF#1949  -  []  202.2 238.35 0 top
NOREF#1950  -  []  260.59 184.98 90 top
NOREF#1951  -  []  139.55 180.49 90 top
NOREF#1952  -  []  248.54 267.5 90 top
NOREF#1953  -  []  277.18 236.17 90 top
NOREF#1954  -  []  231.11 258.18 0 top
NOREF#1955  -  []  156.33 167.9 90 top
NOREF#1956  -  []  275.92 255.7 90 top
NOREF#1957  -  []  152.61 456.29 0 top
NOREF#1958  -  []  175.65 244.35 0 top
NOREF#1959  -  []  205.38 226.23 0 top
NOREF#1960  -  []  148.44 241.72 90 top
NOREF#1961  -  []  122.85 281.02 0 top
NOREF#1962  -  []  199.27 211.67 0 top
NOREF#1963  -  []  226.43 222.5 90 top
NOREF#1964  -  []  264.16 185.63 90 top
NOREF#1965  -  []  207.95 226.12 90 top
NOREF#1966  -  []  157.8 14.59 90 top
NOREF#1967  -  []  201.84 235.2 0 top
NOREF#1968  -  []  236.02 197.6 0 top
NOREF#1969  -  []  173.65 179.15 0 top
NOREF#1970  -  []  273.76 190.88 90 top
NOREF#1971  -  []  149.72 215.77 0 top
NOREF#1972  -  []  186.16 286.14 90 top
NOREF#1973  -  []  210.02 214.45 0 top
NOREF#1974  -  []  267.3 220.35 0 top
NOREF#1975  -  []  223.36 198.18 0 top
NOREF#1976  -  []  149.84 284.11 90 top
NOREF#1977  -  []  226.7 297.01 90 top
NOREF#1978  -  []  157.25 251.93 0 top
NOREF#1979  -  []  191.18 239.15 0 top
NOREF#1980  -  []  147.03 231.4 0 top
NOREF#1981  -  []  273.39 253.03 90 top
NOREF#1982  -  []  143.49 247.06 90 top
NOREF#1983  -  []  276.57 242.05 0 top
NOREF#1984  -  []  164.95 264.23 90 top
NOREF#1985  -  []  248.42 201.77 0 top
NOREF#1986  -  []  266.16 200.17 90 top
NOREF#1987  -  []  199.22 195.7 90 top
NOREF#1988  -  []  269.12 180.3 90 top
NOREF#1989  -  []  178.97 211.91 90 top
NOREF#1990  -  []  290.89 202.32 0 top
NOREF#1991  -  []  270.86 82.65 0 top
NOREF#1992  -  []  166.32 269.17 0 top
NOREF#1993  -  []  135.66 244.35 0 top
NOREF#1994  -  []  169.49 280.89 0 top
NOREF#1995  -  []  236.45 247.71 0 top
NOREF#1996  -  []  264.04 245.96 0 top
NOREF#1997  -  []  247.04 299.09 0 top
NOREF#1998  -  []  266.43 282.49 90 top
NOREF#1999  -  []  251.25 184.35 0 top
NOREF#2000  -  []  275.17 212.18 0 top
NOREF#2001  -  []  192.25 282.59 90 top
NOREF#2002  -  []  199.65 212.56 0 top
NOREF#2003  -  []  228.44 257.85 90 top
NOREF#2004  -  []  219.55 180.49 90 top
NOREF#2005  -  []  273.26 456.29 0 top
NOREF#2006  -  []  147.77 251.31 0 top
NOREF#2007  -  []  142.81 197.6 0 top
NOREF#2008  -  []  230.56 192.78 0 top
NOREF#2009  -  []  241.84 235.2 0 top
NOREF#2010  -  []  191.95 178.07 0 top
NOREF#2011  -  []  232.25 222.59 90 top
NOREF#2012  -  []  274.33 204.33 90 top
NOREF#2013  -  []  151.11 200.17 90 top
NOREF#2014  -  []  202.2 238.35 0 top
NOREF#2015  -  []  181.55 265.11 90 top
NOREF#2016  -  []  196.57 253.35 0 top
NOREF#2017  -  []  199.06 238.07 0 top
NOREF#2018  -  []  148.35 223.79 90 top
NOREF#2019  -  []  243.84 205.58 0 top
NOREF#2020  -  []  164.64 241.15 90 top
NOREF#2021  -  []  260.95 204.09 90 top
NOREF#2022  -  []  271.79 196.75 0 top
NOREF#2023  -  []  197.03 178.07 0 top
NOREF#2024  -  []  151.79 251.93 0 top
NOREF#2025  -  []  194.07 251.6 90 top
NOREF#2026  -  []  273.18 277.69 90 top
NOREF#2027  -  []  135.24 201.55 90 top
NOREF#2028  -  []  157.03 238.07 0 top
NOREF#2029  -  []  129.05 292.28 0 top
NOREF#2030  -  []  275.17 221.32 0 top
NOREF#2031  -  []  195.92 190.88 90 top
NOREF#2032  -  []  183.49 247.06 90 top
NOREF#2033  -  []  257.25 176.5 90 top
NOREF#2034  -  []  273.94 256.75 0 top
NOREF#2035  -  []  130.02 274.45 0 top
NOREF#2036  -  []  227.43 278.27 0 top
NOREF#2037  -  []  263.36 193.35 0 top
NOREF#2038  -  []  266.28 193.03 90 top
NOREF#2039  -  []  174.09 207.27 90 top
NOREF#2040  -  []  235.17 276.75 90 top
NOREF#2041  -  []  258.95 208.91 0 top
NOREF#2042  -  []  227.99 178.35 0 top
NOREF#2043  -  []  199.44 239.15 0 top
NOREF#2044  -  []  190.88 168.6 90 top
NOREF#2045  -  []  270.41 168.7 90 top
NOREF#2046  -  []  216.55 220.49 0 top
NOREF#2047  -  []  277.92 190.01 0 top
NOREF#2048  -  []  163.97 265.9 0 top
NOREF#2049  -  []  135.24 261.55 90 top
NOREF#2050  -  []  173.78 207.01 0 top
NOREF#2051  -  []  155.68 173.69 0 top
NOREF#2052  -  []  232.25 212.18 90 top
NOREF#2053  -  []  233.94 251.93 0 top
NOREF#2054  -  []  236.81 232.54 0 top
NOREF#2055  -  []  255.02 268.14 90 top
NOREF#2056  -  []  188.44 193.03 90 top
NOREF#2057  -  []  140.83 208.59 90 top
NOREF#2058  -  []  151.76 227.33 0 top
NOREF#2059  -  []  194.07 196.43 90 top
NOREF#2060  -  []  193.83 232.21 90 top
NOREF#2061  -  []  203.84 268.62 0 top
NOREF#2062  -  []  164.95 207.27 90 top
NOREF#2063  -  []  135.15 260.67 0 top
NOREF#2064  -  []  130.92 291.95 90 top
NOREF#2065  -  []  239.4 260.64 90 top
NOREF#2066  -  []  181.6 308.11 0 top
NOREF#2067  -  []  275.92 195.7 90 top
NOREF#2068  -  []  279.27 271.67 0 top
NOREF#2069  -  []  277.37 251.6 90 top
NOREF#2070  -  []  141.6 248.12 0 top
NOREF#2071  -  []  230.15 206.89 90 top
NOREF#2072  -  []  148.32 185.63 0 top
NOREF#2073  -  []  277.18 176.17 90 top
NOREF#2074  -  []  236.7 257.85 90 top
NOREF#2075  -  []  268.44 197.85 90 top
NOREF#2076  -  []  146.16 253.35 0 top
NOREF#2077  -  []  248.54 200.64 90 top
NOREF#2078  -  []  221.85 292.49 0 top
NOREF#2079  -  []  162.26 236.17 90 top
NOREF#2080  -  []  187.77 181.47 0 top
NOREF#2081  -  []  270.98 184.35 0 top
NOREF#2082  -  []  232.25 282.59 0 top
NOREF#2083  -  []  148.95 206.89 0 top
NOREF#2084  -  []  194.39 276.17 90 top
NOREF#2085  -  []  166.32 212.22 0 top
NOREF#2086  -  []  231.19 283.92 0 top
NOREF#2087  -  []  213.78 267.01 0 top
NOREF#2088  -  []  263.49 193.03 90 top
NOREF#2089  -  []  283.97 268.95 0 top
NOREF#2090  -  []  153.39 257.85 90 top
NOREF#2091  -  []  155.17 216.75 90 top
NOREF#2092  -  []  279.22 255.7 90 top
NOREF#2093  -  []  286.32 272.22 0 top
NOREF#2094  -  []  164.32 291.95 90 top
NOREF#2095  -  []  161.75 209.17 0 top
NOREF#2096  -  []  279.72 279.22 90 top
NOREF#2097  -  []  300.14 320.9 0 top
NOREF#2098  -  []  272.25 212.18 0 top
NOREF#2099  -  []  288.54 260.64 90 top
NOREF#2100  -  []  119.48 456.29 90 top
NOREF#2101  -  []  174.51 263.76 0 top
NOREF#2102  -  []  139.08 201.22 0 top
NOREF#2103  -  []  168.42 208.62 0 top
NOREF#2104  -  []  187.43 224.11 90 top
NOREF#2105  -  []  217.29 247.78 0 top
NOREF#2106  -  []  277.25 191.93 0 top
NOREF#2107  -  []  163.84 205.58 0 top
NOREF#2108  -  []  275.92 190.88 90 top
NOREF#2109  -  []  199.4 262.09 0 top
NOREF#2110  -  []  225.42 214.72 90 top
NOREF#2111  -  []  156.84 167.33 0 top
NOREF#2112  -  []  251.65 233.3 90 top
NOREF#2113  -  []  167.04 239.09 0 top
NOREF#2114  -  []  239.27 204.78 90 top
NOREF#2115  -  []  218.35 271.84 0 top
NOREF#2116  -  []  199.4 212 0 top
NOREF#2117  -  []  195.17 212.18 90 top
NOREF#2118  -  []  134.43 232.23 0 top
NOREF#2119  -  []  229.24 245.31 90 top
NOREF#2120  -  []  159.27 213.41 90 top
NOREF#2121  -  []  275.68 173.69 0 top
NOREF#2122  -  []  269.12 191.6 90 top
NOREF#2123  -  []  268.78 282.65 0 top
NOREF#2124  -  []  270.77 213.37 90 top
NOREF#2125  -  []  265.41 286.99 90 top
NOREF#2126  -  []  194.07 256.43 90 top
NOREF#2127  -  []  244.95 260.42 90 top
NOREF#2128  -  []  183.49 193.03 90 top
NOREF#2129  -  []  225.09 257.49 90 top
NOREF#2130  -  []  140.95 208.91 90 top
NOREF#2131  -  []  136.5 271.94 90 top
NOREF#2132  -  []  192.13 280.09 0 top
NOREF#2133  -  []  188.99 251.93 0 top
NOREF#2134  -  []  229.84 284.11 90 top
NOREF#2135  -  []  156.8 214.65 90 top
NOREF#2136  -  []  190.77 219.22 90 top
NOREF#2137  -  []  272.72 192.78 0 top
NOREF#2138  -  []  209.52 264.23 90 top
NOREF#2139  -  []  152.11 171.4 0 top
NOREF#2140  -  []  259.08 208.59 0 top
NOREF#2141  -  []  268.99 180.62 0 top
NOREF#2142  -  []  204.32 291.95 90 top
NOREF#2143  -  []  231.73 232.54 0 top
NOREF#2144  -  []  221.55 202.57 90 top
NOREF#2145  -  []  88.14 134.87 0 top
NOREF#2146  -  []  239.72 274.65 90 top
NOREF#2147  -  []  154.33 204.33 90 top
NOREF#2148  -  []  255.65 244.35 0 top
NOREF#2149  -  []  153.27 258.18 0 top
NOREF#2150  -  []  147.99 178.35 0 top
NOREF#2151  -  []  263.36 247.38 0 top
NOREF#2152  -  []  244.95 204.23 90 top
NOREF#2153  -  []  237.92 190.01 0 top
NOREF#2154  -  []  184.16 245.63 90 top
NOREF#2155  -  []  159.4 213.09 90 top
NOREF#2156  -  []  152.63 233.69 0 top
NOREF#2157  -  []  211.05 229.49 0 top
NOREF#2158  -  []  273.94 191.93 0 top
NOREF#2159  -  []  122.85 237.22 0 top
NOREF#2160  -  []  235.68 173.69 0 top
NOREF#2161  -  []  228.81 190.88 90 top
NOREF#2162  -  []  254.09 260.42 90 top
NOREF#2163  -  []  283.84 200.97 90 top
NOREF#2164  -  []  233.03 232.1 0 top
NOREF#2165  -  []  243.84 274.21 0 top
NOREF#2166  -  []  213.69 14.59 90 top
NOREF#2167  -  []  196.7 241.72 90 top
NOREF#2168  -  []  227.77 241.47 0 top
NOREF#2169  -  []  138.95 208.91 0 top
NOREF#2170  -  []  231.91 256.43 90 top
NOREF#2171  -  []  201.12 248.11 90 top
NOREF#2172  -  []  273.18 217.69 90 top
NOREF#2173  -  []  239.44 239.15 0 top
NOREF#2174  -  []  193.56 173.37 90 top
NOREF#2175  -  []  156.79 171.3 0 top
NOREF#2176  -  []  232.25 282.59 90 top
NOREF#2177  -  []  178.95 208.91 0 top
NOREF#2178  -  []  271.79 191.93 0 top
NOREF#2179  -  []  252.55 190.49 90 top
NOREF#2180  -  []  172.55 190.49 90 top
NOREF#2181  -  []  157.37 180.3 90 top
NOREF#2182  -  []  155.17 276.75 90 top
NOREF#2183  -  []  213.36 201.22 0 top
NOREF#2184  -  []  237.37 240.3 90 top
NOREF#2185  -  []  171.65 233.3 90 top
NOREF#2186  -  []  237.25 256.75 0 top
NOREF#2187  -  []  174.09 260.42 90 top
NOREF#2188  -  []  156.02 192.78 0 top
NOREF#2189  -  []  180.95 261.55 90 top
NOREF#2190  -  []  227.77 252.78 0 top
NOREF#2191  -  []  182.81 192.78 0 top
NOREF#2192  -  []  165.38 226.23 0 top
NOREF#2193  -  []  199.27 268.62 0 top
NOREF#2194  -  []  203.97 272 0 top
NOREF#2195  -  []  242.85 237.22 0 top
NOREF#2196  -  []  196.38 241.15 90 top
NOREF#2197  -  []  242.85 297.22 0 top
NOREF#2198  -  []  139.08 265.79 0 top
NOREF#2199  -  []  148.32 245.63 0 top
NOREF#2200  -  []  168.45 235.2 0 top
NOREF#2201  -  []  289.52 270.32 90 top
NOREF#2202  -  []  179.08 203.76 0 top
NOREF#2203  -  []  192.51 235.77 0 top
NOREF#2204  -  []  89.76 145.32 0 top
NOREF#2205  -  []  163.84 208.62 0 top
NOREF#2206  -  []  279.22 195.7 90 top
NOREF#2207  -  []  289.52 207.27 90 top
NOREF#2208  -  []  275.68 233.69 90 top
NOREF#2209  -  []  203.84 264.78 90 top
NOREF#2210  -  []  226.28 257.85 90 top
NOREF#2211  -  []  229.72 286.19 0 top
NOREF#2212  -  []  151.71 171.3 0 top
NOREF#2213  -  []  210.89 266.13 0 top
NOREF#2214  -  []  232.87 248.11 90 top
NOREF#2215  -  []  199.4 208.95 0 top
NOREF#2216  -  []  197.59 175.77 0 top
NOREF#2217  -  []  233.6 276.55 0 top
NOREF#2218  -  []  162.2 238.35 0 top
NOREF#2219  -  []  199.27 267.82 90 top
NOREF#2220  -  []  254.33 389.27 90 top
NOREF#2221  -  []  239.22 239.57 90 top
NOREF#2222  -  []  179.72 273.6 90 top
NOREF#2223  -  []  122.44 232.28 0 top
NOREF#2224  -  []  279.4 272 0 top
NOREF#2225  -  []  196.79 231.3 0 top
NOREF#2226  -  []  199.72 223.79 90 top
NOREF#2227  -  []  230.77 213.37 90 top
NOREF#2228  -  []  236.38 181.15 90 top
NOREF#2229  -  []  244.61 234.24 90 top
NOREF#2230  -  []  192.25 272.17 90 top
NOREF#2231  -  []  197.92 250.01 0 top
NOREF#2232  -  []  148.44 181.72 90 top
NOREF#2233  -  []  199.22 190.88 90 top
NOREF#2234  -  []  249.05 292.28 0 top
NOREF#2235  -  []  243.92 229.94 0 top
NOREF#2236  -  []  197.37 196.43 90 top
NOREF#2237  -  []  231.79 196.75 0 top
NOREF#2238  -  []  209.55 237.49 90 top
NOREF#2239  -  []  270.56 257.6 0 top
NOREF#2240  -  []  208.54 204.45 90 top
NOREF#2241  -  []  90.49 457.2 0 top
NOREF#2242  -  []  163.97 214.54 0 top
NOREF#2243  -  []  156.7 181.72 90 top
NOREF#2244  -  []  284.95 272.86 90 top
NOREF#2245  -  []  277.71 232.86 0 top
NOREF#2246  -  []  235.05 274.25 0 top
NOREF#2247  -  []  151.46 167 0 top
NOREF#2248  -  []  233.76 255.7 90 top
NOREF#2249  -  []  186.16 226.14 90 top
NOREF#2250  -  []  159.27 205.58 0 top
NOREF#2251  -  []  214.07 210.89 90 top
NOREF#2252  -  []  276.02 241.47 0 top
NOREF#2253  -  []  196.52 285.69 0 top
NOREF#2254  -  []  231.91 196.43 90 top
NOREF#2255  -  []  262.03 289.03 90 top
NOREF#2256  -  []  199.4 207.5 90 top
NOREF#2257  -  []  136.63 292.23 0 top
NOREF#2258  -  []  266.01 250.88 90 top
NOREF#2259  -  []  189.72 281.62 0 top
NOREF#2260  -  []  268.19 247.71 0 top
NOREF#2261  -  []  203.92 229.94 0 top
NOREF#2262  -  []  138.56 246.51 0 top
NOREF#2263  -  []  248.42 207.82 90 top
NOREF#2264  -  []  146.28 253.03 90 top
NOREF#2265  -  []  208.42 205.58 0 top
NOREF#2266  -  []  142.88 226.99 0 top
NOREF#2267  -  []  227.77 257.6 0 top
NOREF#2268  -  []  199.27 265.58 0 top
NOREF#2269  -  []  224.16 251.6 90 top
NOREF#2270  -  []  236.1 280.99 90 top
NOREF#2271  -  []  193.95 196.75 0 top
NOREF#2272  -  []  157.25 256.75 0 top
NOREF#2273  -  []  286.32 262.32 0 top
NOREF#2274  -  []  244.61 294.24 90 top
NOREF#2275  -  []  129.44 260.67 0 top
NOREF#2276  -  []  226.7 223.05 90 top
NOREF#2277  -  []  283.84 213.41 90 top
NOREF#2278  -  []  231.11 253.35 0 top
NOREF#2279  -  []  275.05 223.39 0 top
NOREF#2280  -  []  195.56 235.77 0 top
NOREF#2281  -  []  188.19 247.71 0 top
NOREF#2282  -  []  260.95 261.55 90 top
NOREF#2283  -  []  261.59 234.15 0 top
NOREF#2284  -  []  270.48 175.77 0 top
NOREF#2285  -  []  206.32 274.76 0 top
NOREF#2286  -  []  171.05 229.49 0 top
NOREF#2287  -  []  239.4 208.95 0 top
NOREF#2288  -  []  199.4 265.9 0 top
NOREF#2289  -  []  240.23 176.17 90 top
NOREF#2290  -  []  208.54 268.95 0 top
NOREF#2291  -  []  193.76 195.7 90 top
NOREF#2292  -  []  159.65 272.56 0 top
NOREF#2293  -  []  273.27 258.18 0 top
NOREF#2294  -  []  307.66 457.2 0 top
NOREF#2295  -  []  146.01 195.7 90 top
NOREF#2296  -  []  220.95 206.12 90 top
NOREF#2297  -  []  251.25 244.35 0 top
NOREF#2298  -  []  99.98 392.33 90 top
NOREF#2299  -  []  268.32 185.63 90 top
NOREF#2300  -  []  235.17 272.17 0 top
NOREF#2301  -  []  138.85 241.15 90 top
NOREF#2302  -  []  189.84 219.54 90 top
NOREF#2303  -  []  288.54 262.09 0 top
NOREF#2304  -  []  191.76 227.33 0 top
NOREF#2305  -  []  271.73 232.54 0 top
NOREF#2306  -  []  159.27 210.87 90 top
NOREF#2307  -  []  269.67 250.01 0 top
NOREF#2308  -  []  151.53 233.37 90 top
NOREF#2309  -  []  189.84 219.54 0 top
NOREF#2310  -  []  194.39 226.59 90 top
NOREF#2311  -  []  191.19 278.07 0 top
NOREF#2312  -  []  226.16 253.35 0 top
NOREF#2313  -  []  219.08 201.22 0 top
NOREF#2314  -  []  256.98 265.11 90 top
NOREF#2315  -  []  276.57 185.63 0 top
NOREF#2316  -  []  248.42 204.78 90 top
NOREF#2317  -  []  147.51 252.5 90 top
NOREF#2318  -  []  136.55 280.49 0 top
NOREF#2319  -  []  152.25 278.02 90 top
NOREF#2320  -  []  251.65 293.3 90 top
NOREF#2321  -  []  274.33 207.37 90 top
NOREF#2322  -  []  155.92 195.7 90 top
NOREF#2323  -  []  197.37 256.43 90 top
NOREF#2324  -  []  288.42 207.82 90 top
NOREF#2325  -  []  144.04 256.75 0 top
NOREF#2326  -  []  204.95 260.42 90 top
NOREF#2327  -  []  159.27 200.97 90 top
NOREF#2328  -  []  193.95 191.93 0 top
NOREF#2329  -  []  152.25 218.02 90 top
NOREF#2330  -  []  124.61 294.89 90 top
NOREF#2331  -  []  271.11 253.35 0 top
NOREF#2332  -  []  236.02 257.6 0 top
NOREF#2333  -  []  233.6 222.39 0 top
NOREF#2334  -  []  233.56 233.37 90 top
NOREF#2335  -  []  192.13 214.25 0 top
NOREF#2336  -  []  159.72 214.65 90 top
NOREF#2337  -  []  131.84 21.69 90 top
NOREF#2338  -  []  152.25 278.02 0 top
NOREF#2339  -  []  279.4 210.55 90 top
NOREF#2340  -  []  209.55 237.49 0 top
NOREF#2341  -  []  279.27 270.87 90 top
NOREF#2342  -  []  259.4 458.49 0 top
NOREF#2343  -  []  230.88 168.6 90 top
NOREF#2344  -  []  212.64 204.47 0 top
NOREF#2345  -  []  203.4 296.38 0 top
NOREF#2346  -  []  203.97 212 0 top
NOREF#2347  -  []  181.55 262.57 90 top
NOREF#2348  -  []  230.41 228.7 90 top
NOREF#2349  -  []  195.17 216.75 0 top
NOREF#2350  -  []  254 14.59 90 top
NOREF#2351  -  []  220.83 208.59 90 top
NOREF#2352  -  []  148.78 228.49 0 top
NOREF#2353  -  []  169.52 212.86 90 top
NOREF#2354  -  []  158.91 172.21 90 top
NOREF#2355  -  []  196.45 187.71 0 top
NOREF#2356  -  []  172.64 204.47 0 top
NOREF#2357  -  []  151.24 197.85 90 top
NOREF#2358  -  []  147.43 218.27 90 top
NOREF#2359  -  []  155.96 168.6 90 top
NOREF#2360  -  []  203.97 260.64 90 top
NOREF#2361  -  []  222.81 246.81 0 top
NOREF#2362  -  []  198.11 232.1 0 top
NOREF#2363  -  []  146.96 191.6 90 top
NOREF#2364  -  []  191.11 193.35 0 top
NOREF#2365  -  []  156.1 220.99 90 top
NOREF#2366  -  []  144.04 196.75 0 top
NOREF#2367  -  []  244.95 210.32 90 top
NOREF#2368  -  []  208.54 208.95 0 top
NOREF#2369  -  []  189.84 213.7 0 top
NOREF#2370  -  []  192.25 278.02 0 top
NOREF#2371  -  []  193.18 222.26 90 top
NOREF#2372  -  []  199.27 200.97 90 top
NOREF#2373  -  []  192.25 212.18 90 top
